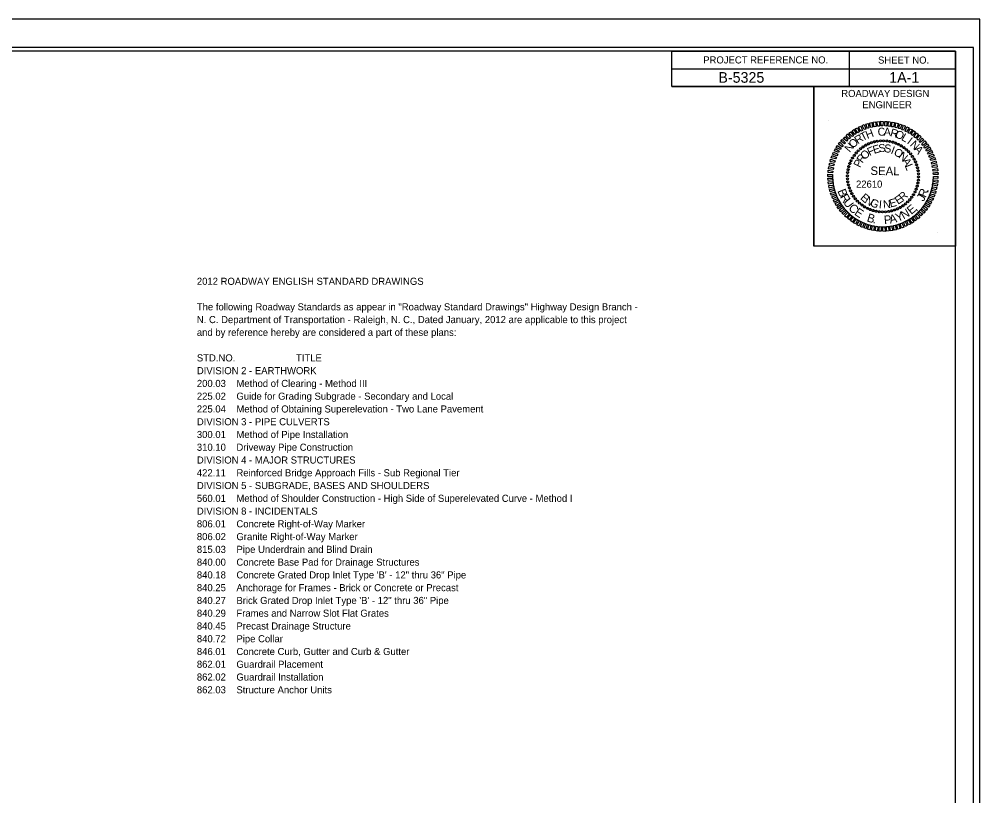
# Model space of a CAD drawing. Extents: x 9834 to 11517, y 9978 to 11072.
# Drawn here: x 10840 to 11517, y 10525 to 11072 of the extents above; entities that cross this region are included whole.
import ezdxf

# ---------------------------------------------------------------- set-up
doc = ezdxf.new("R2010")
doc.units = 0
for name, color, linetype in [('Default', 7, 'Continuous'), ('Scratch_Level_0', 7, 'Continuous'), ('Sheet Cutting Line CELL', 7, 'Continuous'), ('Sheet Data Field CELL', 7, 'Continuous'), ('Sheet PE Seal CELL', 7, 'Continuous'), ('Sheet Plan CELL', 7, 'Continuous'), ('Sheet Plot Border Inside CELL', 7, 'Continuous'), ('Sheet Plot Border Outside CELL', 7, 'Continuous')]:
    doc.layers.add(name, color=color, linetype=linetype)

msp = doc.modelspace()

# ---------------------------------------------------------------- linework, layer by layer
at = {"layer": 'Scratch_Level_0'}
msp.add_arc((11448.79, 10961.72), 35.5, 180, 360, dxfattribs=at)
at = {"layer": 'Sheet Cutting Line CELL'}
msp.add_line((11517, 11072.5), (9833.5, 11072.5), dxfattribs=at)
at = {"layer": 'Sheet PE Seal CELL'}
for p, q in [((11410.69, 11001.42), (11410.69, 11001.42)), ((11438.59, 10984.67), (11438.59, 10984.67)), ((11440.59, 10985.47), (11440.59, 10985.47)), ((11442.69, 10986.07), (11442.69, 10986.07)), ((11444.89, 10986.47), (11444.89, 10986.47)), ((11447.04, 10986.77), (11447.04, 10986.77)), ((11449.24, 10986.82), (11449.24, 10986.82)), ((11451.44, 10986.67), (11451.44, 10986.67)), ((11453.59, 10986.32), (11453.59, 10986.32)), ((11455.69, 10985.87), (11455.69, 10985.87)), ((11457.79, 10985.17), (11457.79, 10985.17)), ((11459.79, 10984.27), (11459.79, 10984.27)), ((11429.84, 10978.22), (11429.84, 10978.22)), ((11431.34, 10979.77), (11431.34, 10979.77)), ((11432.99, 10981.27), (11432.99, 10981.27)), ((11434.74, 10982.52), (11434.74, 10982.52)), ((11436.64, 10983.67), (11436.64, 10983.67)), ((11461.74, 10983.27), (11461.74, 10983.27)), ((11463.54, 10982.02), (11463.54, 10982.02)), ((11465.29, 10980.67), (11465.29, 10980.67)), ((11466.84, 10979.17), (11466.84, 10979.17)), ((11468.34, 10977.52), (11468.34, 10977.52)), ((11425.34, 10970.72), (11425.34, 10970.72)), ((11426.24, 10972.72), (11426.24, 10972.72)), ((11427.24, 10974.67), (11427.24, 10974.67)), ((11428.49, 10976.47), (11428.49, 10976.47)), ((11469.59, 10975.77), (11469.59, 10975.77)), ((11470.74, 10973.87), (11470.74, 10973.87)), ((11471.74, 10971.92), (11471.74, 10971.92)), ((11423.84, 10964.37), (11423.84, 10964.37)), ((11424.19, 10966.52), (11424.19, 10966.52)), ((11424.64, 10968.62), (11424.64, 10968.62)), ((11472.54, 10969.92), (11472.54, 10969.92)), ((11473.14, 10967.82), (11473.14, 10967.82)), ((11473.54, 10965.62), (11473.54, 10965.62)), ((11423.69, 10962.17), (11423.69, 10962.17)), ((11423.74, 10959.97), (11423.74, 10959.97)), ((11424.04, 10957.82), (11424.04, 10957.82)), ((11448.79, 10961.72), (11448.79, 10961.72)), ((11473.74, 10959.07), (11473.74, 10959.07)), ((11473.84, 10963.47), (11473.84, 10963.47)), ((11473.89, 10961.27), (11473.89, 10961.27)), ((11424.44, 10955.62), (11424.44, 10955.62)), ((11425.04, 10953.52), (11425.04, 10953.52)), ((11425.84, 10951.52), (11425.84, 10951.52)), ((11471.34, 10950.72), (11471.34, 10950.72)), ((11472.24, 10952.72), (11472.24, 10952.72)), ((11472.94, 10954.82), (11472.94, 10954.82)), ((11473.39, 10956.92), (11473.39, 10956.92)), ((11426.84, 10949.57), (11426.84, 10949.57)), ((11427.99, 10947.67), (11427.99, 10947.67)), ((11429.24, 10945.92), (11429.24, 10945.92)), ((11430.74, 10944.27), (11430.74, 10944.27)), ((11466.24, 10943.67), (11466.24, 10943.67)), ((11467.74, 10945.22), (11467.74, 10945.22)), ((11469.09, 10946.97), (11469.09, 10946.97)), ((11470.34, 10948.77), (11470.34, 10948.77)), ((11432.29, 10942.77), (11432.29, 10942.77)), ((11434.04, 10941.42), (11434.04, 10941.42)), ((11435.84, 10940.17), (11435.84, 10940.17)), ((11437.79, 10939.17), (11437.79, 10939.17)), ((11439.79, 10938.27), (11439.79, 10938.27)), ((11441.89, 10937.57), (11441.89, 10937.57)), ((11443.99, 10937.12), (11443.99, 10937.12)), ((11452.69, 10936.97), (11452.69, 10936.97)), ((11454.89, 10937.37), (11454.89, 10937.37)), ((11456.99, 10937.97), (11456.99, 10937.97)), ((11458.99, 10938.77), (11458.99, 10938.77)), ((11460.94, 10939.77), (11460.94, 10939.77)), ((11462.84, 10940.92), (11462.84, 10940.92)), ((11464.59, 10942.17), (11464.59, 10942.17)), ((11446.14, 10936.77), (11446.14, 10936.77)), ((11448.34, 10936.62), (11448.34, 10936.62)), ((11450.54, 10936.67), (11450.54, 10936.67)), ((11486.89, 10922.02), (11486.89, 10922.02))]:
    msp.add_line(p, q, dxfattribs=at)
for points in [[(11435.44, 10994.72), (11434.14, 10997.62), (11435.64, 10998.22), (11436.69, 10995.02)], [(11437.89, 10995.52), (11436.74, 10998.52), (11438.29, 10998.97), (11438.94, 10995.87)], [(11440.29, 10996.17), (11439.24, 10999.32), (11440.94, 10999.67), (11441.34, 10996.42)], [(11442.69, 10996.72), (11441.89, 10999.92), (11443.54, 11000.07), (11443.89, 10996.87)], [(11445.09, 10997.02), (11444.54, 11000.22), (11446.24, 11000.42), (11446.29, 10997.17)], [(11447.59, 10997.27), (11447.34, 11000.52), (11448.99, 11000.47), (11448.79, 10997.22)], [(11449.99, 10997.22), (11449.99, 11000.47), (11451.64, 11000.42), (11451.19, 10997.17)], [(11452.49, 10997.07), (11452.69, 11000.32), (11454.34, 11000.02), (11453.69, 10996.87)], [(11454.89, 10996.67), (11455.34, 10999.87), (11456.99, 10999.62), (11456.09, 10996.52)], [(11457.44, 10996.12), (11457.94, 10999.37), (11459.64, 10998.97), (11458.49, 10995.87)], [(11459.84, 10995.47), (11460.59, 10998.57), (11462.14, 10998.07), (11460.89, 10995.12)], [(11424.99, 10988.17), (11422.79, 10990.37), (11423.99, 10991.57), (11425.94, 10988.87)], [(11426.99, 10989.72), (11424.84, 10992.12), (11426.19, 10993.17), (11427.94, 10990.37)], [(11428.89, 10991.22), (11427.04, 10993.77), (11428.34, 10994.72), (11429.99, 10991.82)], [(11431.09, 10992.47), (11429.24, 10995.17), (11430.79, 10995.97), (11432.04, 10993.07)], [(11433.24, 10993.67), (11431.64, 10996.47), (11433.19, 10997.17), (11434.34, 10994.12)], [(11462.09, 10994.57), (11463.24, 10997.72), (11464.64, 10997.12), (11463.24, 10994.22)], [(11464.34, 10993.62), (11465.59, 10996.57), (11467.14, 10995.87), (11465.44, 10993.07)], [(11466.64, 10992.47), (11467.99, 10995.32), (11469.49, 10994.47), (11467.59, 10991.87)], [(11468.59, 10991.12), (11470.34, 10994.02), (11471.64, 10992.97), (11469.69, 10990.52)], [(11470.64, 10989.62), (11472.49, 10992.37), (11473.79, 10991.27), (11471.59, 10988.92)], [(11420.09, 10982.62), (11417.39, 10984.32), (11418.34, 10985.77), (11420.74, 10983.57)], [(11421.59, 10984.52), (11418.99, 10986.47), (11420.09, 10987.77), (11422.29, 10985.42)], [(11423.34, 10986.42), (11420.79, 10988.47), (11422.04, 10989.62), (11424.14, 10987.22)], [(11472.54, 10988.07), (11474.59, 10990.67), (11475.79, 10989.47), (11473.49, 10987.32)], [(11474.34, 10986.32), (11476.49, 10988.67), (11477.69, 10987.47), (11475.09, 10985.52)], [(11476.09, 10984.52), (11478.39, 10986.77), (11479.44, 10985.42), (11476.79, 10983.52)], [(11477.59, 10982.57), (11480.04, 10984.67), (11480.99, 10983.22), (11478.19, 10981.62)], [(11416.39, 10976.17), (11413.29, 10977.32), (11414.04, 10978.87), (11416.89, 10977.27)], [(11417.39, 10978.47), (11414.54, 10979.72), (11415.29, 10981.27), (11417.99, 10979.42)], [(11418.59, 10980.62), (11415.79, 10982.12), (11416.79, 10983.52), (11419.39, 10981.52)], [(11478.89, 10980.52), (11481.54, 10982.42), (11482.49, 10980.92), (11479.59, 10979.52)], [(11480.19, 10978.32), (11482.99, 10980.07), (11483.64, 10978.52), (11480.79, 10977.37)], [(11481.19, 10976.17), (11484.14, 10977.67), (11484.79, 10976.07), (11481.69, 10975.07)], [(11413.99, 10969.17), (11410.89, 10969.57), (11411.24, 10971.27), (11414.39, 10970.22)], [(11414.64, 10971.57), (11411.54, 10972.22), (11411.89, 10973.87), (11415.04, 10972.62)], [(11415.39, 10973.97), (11412.29, 10974.87), (11412.94, 10976.42), (11415.94, 10975.02)], [(11482.09, 10973.82), (11485.14, 10975.12), (11485.69, 10973.57), (11482.59, 10972.77)], [(11482.89, 10971.42), (11486.09, 10972.57), (11486.39, 10970.92), (11483.24, 10970.37)], [(11413.34, 10964.22), (11410.09, 10964.32), (11410.19, 10965.97), (11413.44, 10965.42)], [(11413.59, 10966.62), (11410.39, 10966.92), (11410.59, 10968.62), (11413.84, 10967.82)], [(11483.49, 10969.02), (11486.64, 10969.97), (11486.94, 10968.27), (11483.79, 10967.97)], [(11483.94, 10966.62), (11487.19, 10967.32), (11487.34, 10965.62), (11484.14, 10965.42)], [(11484.24, 10964.22), (11487.49, 10964.62), (11487.59, 10962.92), (11484.34, 10963.02)], [(11413.34, 10959.22), (11410.09, 10958.82), (11409.99, 10960.52), (11413.24, 10960.42)], [(11413.29, 10961.72), (11410.04, 10961.57), (11410.04, 10963.27), (11413.29, 10962.92)], [(11413.64, 10956.82), (11410.39, 10956.12), (11410.24, 10957.82), (11413.44, 10958.02)], [(11484.24, 10959.22), (11487.49, 10959.12), (11487.39, 10957.47), (11484.14, 10958.02)], [(11484.29, 10961.72), (11487.54, 10961.87), (11487.54, 10960.17), (11484.29, 10960.52)], [(11414.09, 10954.42), (11410.94, 10953.47), (11410.64, 10955.17), (11413.79, 10955.47)], [(11414.69, 10952.02), (11411.49, 10950.87), (11411.19, 10952.52), (11414.34, 10953.07)], [(11415.49, 10949.62), (11412.44, 10948.32), (11411.89, 10949.87), (11414.99, 10950.67)], [(11482.94, 10951.87), (11486.04, 10951.22), (11485.69, 10949.57), (11482.54, 10950.82)], [(11483.59, 10954.27), (11486.69, 10953.87), (11486.34, 10952.17), (11483.19, 10953.22)], [(11483.99, 10956.82), (11487.19, 10956.52), (11486.99, 10954.82), (11483.74, 10955.62)], [(11416.39, 10947.27), (11413.44, 10945.77), (11412.79, 10947.37), (11415.89, 10948.37)], [(11417.39, 10945.12), (11414.59, 10943.37), (11413.94, 10944.92), (11416.79, 10946.07)], [(11418.69, 10942.92), (11416.04, 10941.02), (11415.09, 10942.52), (11417.99, 10943.92)], [(11480.19, 10944.97), (11483.04, 10943.72), (11482.29, 10942.17), (11479.59, 10944.02)], [(11481.19, 10947.27), (11484.29, 10946.12), (11483.54, 10944.57), (11480.69, 10946.17)], [(11482.19, 10949.47), (11485.29, 10948.57), (11484.64, 10947.02), (11481.64, 10948.42)], [(11419.99, 10940.87), (11417.54, 10938.77), (11416.59, 10940.22), (11419.39, 10941.82)], [(11421.49, 10938.92), (11419.19, 10936.67), (11418.14, 10938.02), (11420.79, 10939.92)], [(11423.24, 10937.12), (11421.09, 10934.77), (11419.89, 10935.97), (11422.49, 10937.92)], [(11474.24, 10937.02), (11476.79, 10934.97), (11475.54, 10933.82), (11473.44, 10936.22)], [(11475.99, 10938.92), (11478.59, 10936.97), (11477.49, 10935.67), (11475.29, 10938.02)], [(11477.49, 10940.82), (11480.19, 10939.12), (11479.24, 10937.67), (11476.84, 10939.87)], [(11478.99, 10942.82), (11481.79, 10941.32), (11480.79, 10939.92), (11478.19, 10941.92)], [(11425.04, 10935.37), (11422.99, 10932.77), (11421.79, 10933.97), (11424.09, 10936.12)], [(11426.94, 10933.82), (11425.09, 10931.07), (11423.79, 10932.17), (11425.99, 10934.52)], [(11428.99, 10932.32), (11427.24, 10929.42), (11425.94, 10930.47), (11427.89, 10932.92)], [(11430.94, 10930.97), (11429.59, 10928.12), (11428.09, 10928.97), (11429.99, 10931.57)], [(11433.24, 10929.82), (11431.99, 10926.87), (11430.44, 10927.57), (11432.14, 10930.37)], [(11466.49, 10930.97), (11468.34, 10928.27), (11466.79, 10927.47), (11465.54, 10930.37)], [(11468.69, 10932.22), (11470.54, 10929.67), (11469.24, 10928.72), (11467.59, 10931.62)], [(11470.59, 10933.72), (11472.74, 10931.32), (11471.39, 10930.27), (11469.64, 10933.07)], [(11472.59, 10935.27), (11474.79, 10933.07), (11473.59, 10931.87), (11471.64, 10934.57)], [(11435.49, 10928.87), (11434.34, 10925.72), (11432.94, 10926.32), (11434.34, 10929.22)], [(11437.74, 10927.97), (11436.99, 10924.87), (11435.44, 10925.37), (11436.69, 10928.32)], [(11440.14, 10927.32), (11439.64, 10924.07), (11437.94, 10924.47), (11439.09, 10927.57)], [(11442.69, 10926.77), (11442.24, 10923.57), (11440.59, 10923.82), (11441.49, 10926.92)], [(11445.09, 10926.37), (11444.89, 10923.12), (11443.24, 10923.42), (11443.89, 10926.57)], [(11447.59, 10926.22), (11447.59, 10922.97), (11445.94, 10923.02), (11446.39, 10926.27)], [(11449.99, 10926.17), (11450.24, 10922.92), (11448.59, 10922.97), (11448.79, 10926.22)], [(11452.49, 10926.42), (11453.04, 10923.22), (11451.34, 10923.02), (11451.29, 10926.27)], [(11454.89, 10926.72), (11455.69, 10923.52), (11454.04, 10923.37), (11453.69, 10926.57)], [(11457.29, 10927.27), (11458.34, 10924.12), (11456.64, 10923.77), (11456.24, 10927.02)], [(11459.69, 10927.92), (11460.84, 10924.92), (11459.29, 10924.47), (11458.64, 10927.57)], [(11462.14, 10928.72), (11463.44, 10925.82), (11461.94, 10925.22), (11460.89, 10928.42)], [(11464.34, 10929.77), (11465.94, 10926.97), (11464.39, 10926.27), (11463.24, 10929.32)]]:
    msp.add_lwpolyline(points, close=True, dxfattribs=at)
for centre, major_axis in [((11436.63, 10983.66), (-0.349, 0.63)), ((11438.59, 10984.63), (-0.293, 0.658)), ((11440.62, 10985.43), (-0.234, 0.681)), ((11442.72, 10986.06), (-0.174, 0.699)), ((11444.86, 10986.49), (-0.113, 0.711)), ((11447.04, 10986.74), (-0.05, 0.718)), ((11449.22, 10986.8), (0.013, 0.72)), ((11451.41, 10986.66), (0.075, 0.716)), ((11453.57, 10986.34), (0.137, 0.707)), ((11455.7, 10985.83), (0.198, 0.692)), ((11457.77, 10985.14), (0.258, 0.672)), ((11459.78, 10984.26), (0.316, 0.647)), ((11429.86, 10978.17), (-0.543, 0.472)), ((11431.36, 10979.76), (-0.5, 0.518)), ((11433, 10981.21), (-0.453, 0.56)), ((11434.76, 10982.51), (-0.403, 0.597)), ((11461.7, 10983.22), (0.371, 0.617)), ((11463.53, 10982.01), (0.423, 0.582)), ((11465.24, 10980.65), (0.472, 0.543)), ((11466.83, 10979.14), (0.518, 0.5)), ((11468.28, 10977.5), (0.56, 0.453)), ((11425.37, 10970.71), (-0.672, 0.258)), ((11426.24, 10972.72), (-0.647, 0.316)), ((11427.29, 10974.64), (-0.617, 0.371)), ((11428.5, 10976.46), (-0.582, 0.423)), ((11469.58, 10975.75), (0.597, 0.403)), ((11470.72, 10973.88), (0.63, 0.349)), ((11471.7, 10971.92), (0.658, 0.293)), ((11472.5, 10969.89), (0.681, 0.234)), ((11423.84, 10964.34), (-0.716, 0.075)), ((11424.17, 10966.51), (-0.707, 0.137)), ((11424.68, 10968.63), (-0.692, 0.198)), ((11473.12, 10967.79), (0.699, 0.174)), ((11473.56, 10965.64), (0.711, 0.113)), ((11473.81, 10963.47), (0.718, 0.05)), ((11423.71, 10962.16), (-0.72, 0.013)), ((11423.77, 10959.97), (-0.718, -0.05)), ((11424.02, 10957.8), (-0.711, -0.113)), ((11473.41, 10956.94), (0.707, -0.137)), ((11473.73, 10959.1), (0.716, -0.075)), ((11473.86, 10961.28), (0.72, -0.013)), ((11424.45, 10955.65), (-0.699, -0.174)), ((11425.07, 10953.56), (-0.681, -0.234)), ((11425.87, 10951.52), (-0.658, -0.293)), ((11426.85, 10949.56), (-0.63, -0.349)), ((11471.33, 10950.73), (0.647, -0.316)), ((11472.2, 10952.73), (0.672, -0.258)), ((11472.89, 10954.81), (0.692, -0.198)), ((11427.99, 10947.7), (-0.597, -0.403)), ((11429.3, 10945.94), (-0.56, -0.453)), ((11430.75, 10944.3), (-0.518, -0.5)), ((11466.21, 10943.68), (0.5, -0.518)), ((11467.71, 10945.27), (0.543, -0.472)), ((11469.08, 10946.98), (0.582, -0.423)), ((11470.28, 10948.8), (0.617, -0.371)), ((11432.33, 10942.79), (-0.472, -0.543)), ((11434.04, 10941.43), (-0.423, -0.582)), ((11435.87, 10940.22), (-0.371, -0.617)), ((11437.79, 10939.18), (-0.316, -0.647)), ((11439.8, 10938.31), (-0.258, -0.672)), ((11441.87, 10937.61), (-0.198, -0.692)), ((11444, 10937.1), (-0.137, -0.707)), ((11446.16, 10936.78), (-0.075, -0.716)), ((11448.35, 10936.64), (-0.013, -0.72)), ((11450.54, 10936.7), (0.05, -0.718)), ((11452.71, 10936.95), (0.113, -0.711)), ((11454.85, 10937.39), (0.174, -0.699)), ((11456.95, 10938.01), (0.234, -0.681)), ((11458.99, 10938.81), (0.293, -0.658)), ((11460.95, 10939.79), (0.349, -0.63)), ((11462.81, 10940.93), (0.403, -0.597)), ((11464.57, 10942.23), (0.453, -0.56))]:
    msp.add_ellipse(centre, major_axis=major_axis, ratio=0.999708, dxfattribs=at)
at = {"layer": 'Sheet Plan CELL'}
for p, q in [((11425, 11049.95), (11425, 11024.95)), ((11299.95, 11037.45), (11500, 11037.45)), ((11299.95, 11024.95), (11500, 11024.95)), ((11299.95, 11024.95), (11500, 11024.95)), ((11400, 11024.95), (11400, 10912.5))]:
    msp.add_line(p, q, dxfattribs=at)
for points in [[(11500, 11050), (10000, 11050), (10000, 10000), (11500, 10000)], [(11299.95, 11050), (11500, 11050), (11500, 11024.95), (11299.95, 11024.95)], [(11400, 11024.95), (11500, 11024.95), (11500, 10912.45), (11400, 10912.45)]]:
    msp.add_lwpolyline(points, close=True, dxfattribs=at)
at = {"layer": 'Sheet Plot Border Inside CELL'}
msp.add_lwpolyline([(9846.5, 9997.5), (11512.5, 9997.5), (11512.5, 11052.5), (9846.5, 11052.5)], close=True, dxfattribs=at)
at = {"layer": 'Sheet Plot Border Outside CELL'}
msp.add_lwpolyline([(9833.5, 9977.5), (11517, 9977.5), (11517, 11072.5), (9833.5, 11072.5)], close=True, dxfattribs=at)

# ---------------------------------------------------------------- texts
at = {"layer": 'Default'}
for s, rotation, p in [('B', 291.48448, (11416.6, 10951.48)), ('R', 66.61137, (11478.82, 10946.27)), ('.', 74.09163, (11480.58, 10950.31)), ('R', 299.18111, (11418.26, 10947.27)), ('U', 306.66137, (11420.4, 10943.41)), ('J', 61.35355, (11477.28, 10943.58)), ('C', 316.59899, (11423.99, 10938.79)), ('E', 326.18114, (11428.15, 10934.98)), ('Y', 21.37125, (11458.96, 10929.51)), ('N', 29.28425, (11463.3, 10931.22)), ('E', 40.01008, (11468.72, 10934.45)), (',', 47.11942, (11471.94, 10937.13)), ('B', 343.49083, (11437.04, 10930.05)), ('P', 5.4216, (11449.72, 10927.96)), ('A', 12.53094, (11453.89, 10928.33)), ('.', 351.18747, (11441.39, 10928.76))]:
    msp.add_text(s, height=6, rotation=rotation, dxfattribs=at).set_placement(p)
for s, p in [('2012 ROADWAY ENGLISH STANDARD DRAWINGS', (10965.38, 10885.23)), ('The following Roadway Standards as appear in "Roadway Standard Drawings" Highway Design Branch -', (10965.38, 10867.23)), ('N. C. Department of Transportation - Raleigh, N. C., Dated January, 2012 are applicable to this project', (10965.38, 10858.23)), ('and by reference hereby are considered a part of these plans:', (10965.38, 10849.23)), ('STD.NO.                       TITLE', (10965.38, 10831.23)), ('DIVISION 2 - EARTHWORK', (10965.38, 10822.23)), ('200.03    Method of Clearing - Method III', (10965.38, 10813.23)), ('225.02    Guide for Grading Subgrade - Secondary and Local', (10965.38, 10804.23)), ('225.04    Method of Obtaining Superelevation - Two Lane Pavement', (10965.38, 10795.23)), ('DIVISION 3 - PIPE CULVERTS', (10965.38, 10786.23)), ('300.01    Method of Pipe Installation ', (10965.38, 10777.23)), ('310.10    Driveway Pipe Construction', (10965.38, 10768.23)), ('DIVISION 4 - MAJOR STRUCTURES', (10965.38, 10759.23)), ('422.11    Reinforced Bridge Approach Fills - Sub Regional Tier', (10965.38, 10750.23)), ('DIVISION 5 - SUBGRADE, BASES AND SHOULDERS', (10965.38, 10741.23)), ('560.01    Method of Shoulder Construction - High Side of Superelevated Curve - Method I', (10965.38, 10732.23)), ('DIVISION 8 - INCIDENTALS', (10965.38, 10723.23)), ('806.01    Concrete Right-of-Way Marker', (10965.38, 10714.23)), ('806.02    Granite Right-of-Way Marker', (10965.38, 10705.23)), ('815.03    Pipe Underdrain and Blind Drain', (10965.38, 10696.23)), ('840.00    Concrete Base Pad for Drainage Structures', (10965.38, 10687.23)), ('840.18    Concrete Grated Drop Inlet Type \'B\' - 12" thru 36" Pipe', (10965.38, 10678.23)), ('840.25    Anchorage for Frames - Brick or Concrete or Precast', (10965.38, 10669.23)), ('840.27    Brick Grated Drop Inlet Type \'B\' - 12" thru 36" Pipe', (10965.38, 10660.23)), ('840.29    Frames and Narrow Slot Flat Grates', (10965.38, 10651.23)), ('840.45    Precast Drainage Structure', (10965.38, 10642.23)), ('840.72    Pipe Collar', (10965.38, 10633.23)), ('846.01    Concrete Curb, Gutter and Curb & Gutter', (10965.38, 10624.23)), ('862.01    Guardrail Placement', (10965.38, 10615.23)), ('862.02    Guardrail Installation', (10965.38, 10606.23)), ('862.03    Structure Anchor Units', (10965.38, 10597.23))]:
    msp.add_text(s, height=5, dxfattribs=at).set_placement(p)
at = {"layer": 'Sheet Data Field CELL'}
for s, p in [('B-5325   ', (11332.83, 11027.7)), ('1A-1', (11453.2, 11027.75))]:
    msp.add_text(s, height=7.5, dxfattribs=at).set_placement(p)
at = {"layer": 'Sheet PE Seal CELL'}
for s, height, rotation, p in [('R', 5.64, 35.02051, (11431.09, 10984.22)), ('T', 5.64, 27.81977, (11434.49, 10986.42)), ('H', 5.64, 20.61948, (11437.74, 10988.07)), ('C', 5.64, 6.21987, (11445.34, 10990.07)), ('A', 5.64, 359.02032, (11449.29, 10990.37)), ('R', 5.64, 344.6211, (11453.49, 10990.17)), ('O', 5.64, 337.42116, (11456.84, 10989.42)), ('L', 5.64, 330.22088, (11461.24, 10987.57)), ('N', 5.64, 49.4235, (11425.34, 10978.22)), ('O', 5.64, 42.22174, (11427.64, 10981.12)), ('E', 5.64, 16.61107, (11442.54, 10977.52)), ('S', 5.64, 7.25561, (11445.99, 10978.57)), ('S', 5.64, 357.9004, (11449.59, 10978.62)), ('I', 5.64, 323.02014, (11465.29, 10985.17)), ('N', 5.64, 315.81891, (11467.44, 10983.62)), ('O', 5.64, 44.68124, (11436.04, 10973.07)), ('F', 5.64, 25.96703, (11439.34, 10976.02)), ('I', 5.64, 339.1896, (11453.89, 10977.92)), ('O', 5.64, 329.83348, (11455.89, 10977.22)), ('N', 5.64, 320.47661, (11459.24, 10975.22)), ('A', 5.64, 308.61715, (11470.39, 10980.67)), ('P', 5.64, 63.39889, (11432.69, 10967.42)), ('R', 5.64, 54.03965, (11434.29, 10970.62)), ('A', 5.64, 301.76027, (11462.09, 10972.62)), ('L', 5.64, 292.40085, (11464.04, 10969.17)), ('SEAL', 5.998, 359, (11439.94, 10962.72)), ('R', 5.64, 42.48141, (11462.89, 10943.97)), ('E', 5.64, 318.27689, (11432.39, 10946.07)), ('N', 5.64, 327.63396, (11435.39, 10943.37)), ('G', 5.64, 336.99024, (11439.19, 10941.12)), ('I', 5.64, 355.7012, (11445.74, 10939.22)), ('N', 5.64, 5.05639, (11449.09, 10939.07)), ('E', 5.64, 14.41176, (11454.04, 10939.67)), ('E', 5.64, 33.12409, (11459.34, 10941.62))]:
    msp.add_text(s, height=height, rotation=rotation, dxfattribs=at).set_placement(p)
msp.add_text('   22610  ', height=4.975, dxfattribs=at).set_placement((11424.28, 10953.77))
at = {"layer": 'Sheet Plan CELL'}
for s, height, p in [('PROJECT REFERENCE NO.', 5.0001, (11322.15, 11041.3)), ('SHEET NO.', 5, (11445.3, 11041.2)), ('ROADWAY DESIGN', 5.0001, (11419.4, 11017.65)), ('ENGINEER', 5, (11434.25, 11009.7))]:
    msp.add_text(s, height=height, dxfattribs=at).set_placement(p)

doc.saveas('drawing.dxf')
